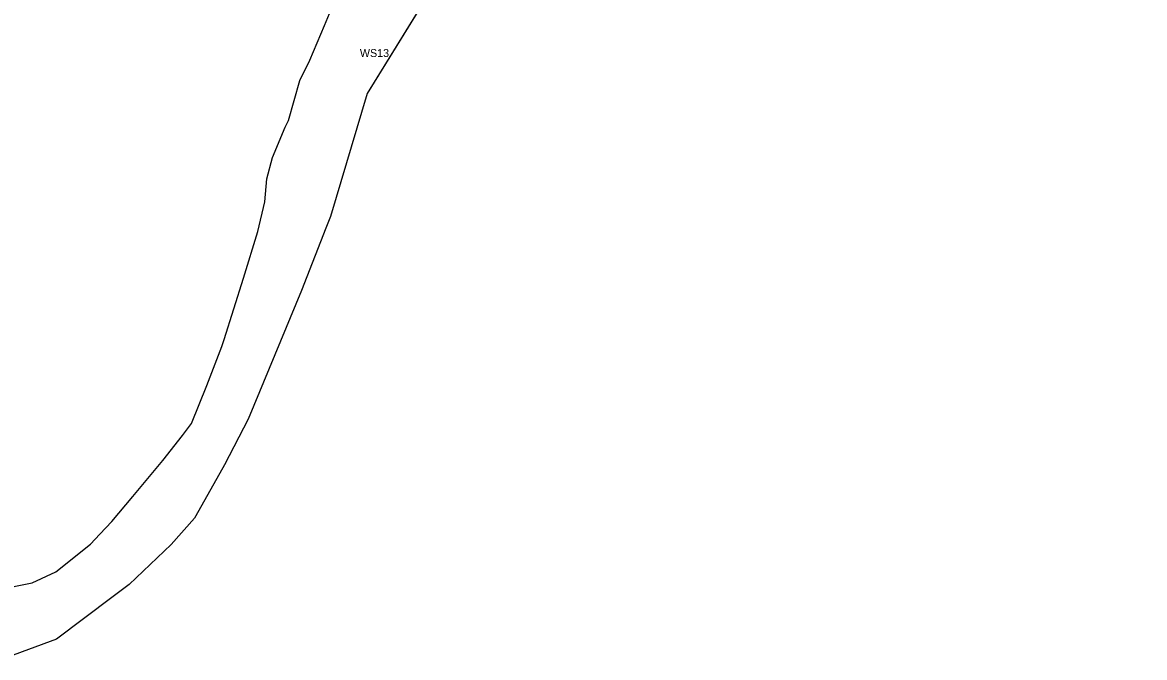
# Model space of a CAD drawing. Extents: x 7428080 to 7432143, y 5545880 to 5549217.
# Drawn here: x 7429439 to 7430217, y 5545899 to 5546339 of the extents above; entities that cross this region are included whole.
import ezdxf

# ---------------------------------------------------------------- set-up
doc = ezdxf.new("R2010")
doc.units = 0
for name, color, linetype in [('CZ_L_granica obszaru objętego planem', 7, 'Continuous'), ('CZ_L_linie rozgraniczające tereny o różnym przeznaczeniu oraz różnych warunkach ich zabudowy i zagospodarowania', 7, 'Continuous'), ('CZ_L_opisy_linie rozgraniczające tereny o różnym przeznaczeniu oraz różnych warunkach ich zabudowy i zagospodarowania', 7, 'Continuous')]:
    doc.layers.add(name, color=color, linetype=linetype)

msp = doc.modelspace()

# ---------------------------------------------------------------- linework, layer by layer
at = {"layer": 'CZ_L_granica obszaru objętego planem'}
for p, q in [((7429752.12, 5546409.83), (7429678.23, 5546289.98)), ((7429678.23, 5546289.98), (7429652.81, 5546204.83)), ((7429652.81, 5546204.83), (7429649.63, 5546196.69)), ((7429649.63, 5546196.69), (7429632.73, 5546153.44)), ((7429632.73, 5546153.44), (7429595.88, 5546064.11)), ((7429595.88, 5546064.11), (7429579.31, 5546032.44)), ((7429579.31, 5546032.44), (7429578.15, 5546030.38)), ((7429578.15, 5546030.38), (7429558.63, 5545995.53)), ((7429558.63, 5545995.53), (7429542.28, 5545977.17)), ((7429542.28, 5545977.17), (7429513.3, 5545949.5)), ((7429513.3, 5545949.5), (7429501.33, 5545940.48)), ((7429501.33, 5545940.48), (7429462.98, 5545911.59)), ((7429462.98, 5545911.59), (7429428.5, 5545898.86))]:
    msp.add_line(p, q, dxfattribs=at)
at = {"layer": 'CZ_L_linie rozgraniczające tereny o różnym przeznaczeniu oraz różnych warunkach ich zabudowy i zagospodarowania'}
for p, q in [((7429648.74, 5546337.15), (7429665.6, 5546378.66)), ((7429638.53, 5546313.19), (7429648.74, 5546337.15)), ((7429631.64, 5546299.18), (7429638.53, 5546313.19)), ((7429623.8, 5546271.25), (7429631.64, 5546299.18)), ((7429612.55, 5546245.72), (7429621.52, 5546266.75)), ((7429621.52, 5546266.75), (7429623.8, 5546271.25)), ((7429608.75, 5546230.83), (7429612.55, 5546245.72)), ((7429607.37, 5546214.85), (7429608.75, 5546230.83)), ((7429602.52, 5546194.32), (7429607.37, 5546214.85)), ((7429592.48, 5546162.06), (7429602.52, 5546194.32)), ((7429579.16, 5546119.57), (7429592.48, 5546162.06)), ((7429577.63, 5546114.7), (7429579.16, 5546119.57)), ((7429567.05, 5546087.51), (7429577.63, 5546114.7)), ((7429556.59, 5546061.16), (7429567.05, 5546087.51)), ((7429550.24, 5546052.94), (7429556.59, 5546061.16)), ((7429536.55, 5546035.44), (7429550.24, 5546052.94)), ((7429515.7, 5546010.54), (7429536.55, 5546035.44)), ((7429501.16, 5545993.18), (7429515.7, 5546010.54)), ((7429492.95, 5545984.55), (7429501.16, 5545993.18)), ((7429462.51, 5545958.24), (7429486.46, 5545977.51)), ((7429486.46, 5545977.51), (7429492.95, 5545984.55)), ((7429446.05, 5545950.62), (7429462.51, 5545958.24)), ((7429420.84, 5545945.53), (7429446.05, 5545950.62))]:
    msp.add_line(p, q, dxfattribs=at)
msp.add_lwpolyline([(7430241.16, 5546589.97), (7430182.29, 5546612.02), (7430136.35, 5546625.79), (7430022.09, 5546625.96), (7429955.41, 5546598.22), (7429920.79, 5546583.82), (7429824.25, 5546508.52), (7429783.16, 5546452.3), (7429752.12, 5546409.83), (7429678.23, 5546289.98), (7429652.81, 5546204.83), (7429649.63, 5546196.69), (7429632.73, 5546153.44), (7429595.88, 5546064.11), (7429579.31, 5546032.44), (7429578.15, 5546030.38), (7429558.63, 5545995.53), (7429542.28, 5545977.17), (7429513.3, 5545949.5), (7429501.33, 5545940.48), (7429462.98, 5545911.59), (7429428.5, 5545898.86)], dxfattribs=at)

# ---------------------------------------------------------------- texts
at = {"layer": 'CZ_L_opisy_linie rozgraniczające tereny o różnym przeznaczeniu oraz różnych warunkach ich zabudowy i zagospodarowania'}
msp.add_text('WS13', height=5.549, dxfattribs=at).set_placement((7429673.24, 5546315.38))

doc.saveas('drawing.dxf')
